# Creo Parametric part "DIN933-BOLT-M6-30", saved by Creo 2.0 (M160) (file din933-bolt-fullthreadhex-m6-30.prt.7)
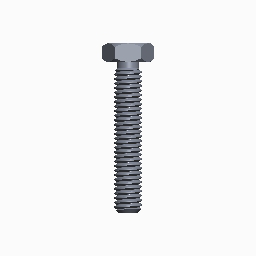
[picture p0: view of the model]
Units: millimeter Kilogram Sec (mmKs); MM, KILOGRAM, SECS

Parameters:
  DESCRIPTION = "PART"
  MODELED_BY = "FI. LAST NAME"
  REV = "TBD"
  ECO_NUMBER = "ECO-00000XXXXX"
  MODELED_DATE = "DD JAN FEB MAR APR MAY JUN JUL AUG SEP OCT NOV DEC 20YY"
  FINISH = "TBD"

Created from: ST.PRT

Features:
  1. datum plane "RIGHT"
  2. datum plane "TOP"
  3. datum plane "FRONT"
  4. datum axis "Z_AXIS"
  5. datum axis "A_1"
  6. datum axis "Y_AXIS"
  7. coordinate system "ASM_CSYS_DEF"
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
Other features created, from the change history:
  sketch "Sketch 1"
  revolve "Revolve 1"
  extrusion "Extrude 1"
  sketch "Sketch 2"
  revolved cut "Revolve 2"
  cut "Helical Sweep 1"
  extrusion "Extrude 2"

Other named items: DATUMS, X_AXIS

Layers: PRT_AXES, PRT_AXES_DEF, PRT_COPY_GEOMETRY, PRT_CURVES, PRT_DATUM_CSYS, PRT_DATUM_CSYS_DEF, PRT_DATUM_PLANES, PRT_DATUM_PLANE_DEF, PRT_DATUM_POINT, PRT_IMPORTS, PRT_MERGE, PRT_QUILTS, PRT_RIBBONS, PRT_SKETCHES, PRT_SOLID_GEOMETRY, PRT_STYLE, PRT_SURFACES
